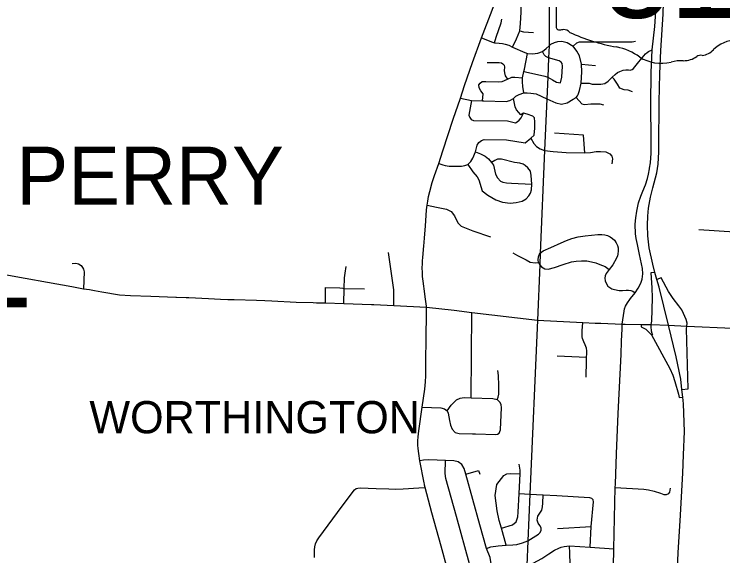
# Model space of a CAD drawing. Extents: x 1755200 to 1902939, y 644115 to 788070.
# Drawn here: x 1808355 to 1819343, y 757899 to 766300 of the extents above; entities that cross this region are included whole.
import ezdxf

# ---------------------------------------------------------------- set-up
doc = ezdxf.new("R2010")
doc.units = 0
for name, color, linetype in [('GM_X_City_Street', 7, 'Continuous'), ('GM_X_Corporation_Text', 7, 'Continuous'), ('GM_X_County_Road', 7, 'Continuous'), ('GM_X_Interchange_Ramps', 7, 'Continuous'), ('GM_X_State_Route', 7, 'Continuous'), ('GM_X_State_Shield', 7, 'Continuous'), ('GM_X_Township', 7, 'Continuous'), ('GM_X_Township_Text', 7, 'Continuous')]:
    doc.layers.add(name, color=color, linetype=linetype)

msp = doc.modelspace()

# ---------------------------------------------------------------- linework, layer by layer
at = {"layer": 'GM_X_City_Street'}
for points in [[(1818228, 764900), (1818228, 764902), (1818231, 765395), (1818249, 765747), (1818286, 766109), (1818306, 766340), (1818311, 766478), (1818310, 766621), (1818297, 766761), (1818273, 766958), (1818252, 767058), (1818227, 767144), (1818174, 767308), (1818073, 767603), (1818052, 767692), (1818038, 767786), (1818032, 767887), (1818045, 768024)], [(1816081, 765789), (1816144, 765918), (1816194, 766040), (1816208, 766154), (1816215, 766329), (1816223, 766542), (1816225, 766641), (1816241, 766690), (1816281, 766722), (1816331, 766734), (1816396, 766731), (1816445, 766743), (1816482, 766777), (1816498, 766825), (1816508, 767121), (1816509, 767181), (1816504, 767217), (1816486, 767247), (1816436, 767277), (1816423, 767280), (1816297, 767296)], [(1814711, 762759), (1814717, 762833), (1814731, 763011), (1814750, 763264), (1814758, 763337), (1814767, 763402), (1814781, 763474), (1814798, 763550), (1814837, 763687), (1814872, 763797), (1814940, 763985), (1814999, 764180), (1815164, 764673), (1815273, 764997), (1815338, 765195), (1815459, 765550), (1815603, 765933), (1815765, 766360), (1815831, 766555), (1815848, 766601), (1815849, 766605)], [(1815803, 765858), (1815827, 765945), (1815907, 766165), (1815916, 766223)], [(1816194, 766040), (1816250, 766024), (1816409, 766017)], [(1815603, 765933), (1815769, 765866), (1815803, 765858), (1815873, 765849), (1815927, 765846), (1815966, 765837), (1816024, 765820), (1816081, 765789), (1816274, 765705), (1816314, 765690), (1816392, 765685), (1816474, 765697), (1816548, 765720), (1816603, 765767), (1816649, 765810), (1816676, 765834), (1816731, 765863), (1816782, 765877), (1816848, 765880), (1816928, 765860), (1817023, 765802)], [(1817023, 765802), (1817078, 765856), (1817122, 765871), (1817301, 765869), (1817937, 765869), (1817986, 765882)], [(1816824, 765236), (1816846, 765322), (1816857, 765495), (1816851, 765534), (1816836, 765558), (1816803, 765577), (1816641, 765624), (1816598, 765642), (1816570, 765670), (1816548, 765720)], [(1817067, 765009), (1817087, 765035), (1817099, 765055), (1817121, 765115), (1817145, 765229), (1817157, 765406), (1817153, 765527), (1817118, 765652), (1817080, 765727), (1817023, 765802)], [(1817145, 765229), (1817268, 765229), (1817319, 765216), (1817384, 765212), (1817453, 765212), (1817515, 765226), (1817566, 765262), (1817628, 765321), (1817671, 765362), (1817711, 765394), (1817744, 765413), (1817797, 765430), (1817841, 765438), (1817878, 765435), (1817908, 765434), (1817936, 765440), (1817957, 765459), (1818040, 765559), (1818145, 765683), (1818169, 765706), (1818191, 765720), (1818249, 765747)], [(1816256, 765082), (1816243, 765180), (1816235, 765252), (1816237, 765313), (1816257, 765412), (1816265, 765445), (1816314, 765690)], [(1815690, 765550), (1815874, 765549), (1815909, 765544), (1815934, 765529), (1815951, 765507), (1815955, 765479), (1815950, 765429), (1815957, 765389), (1815970, 765346), (1816004, 765292)], [(1817153, 765527), (1817370, 765506)], [(1816257, 765412), (1816516, 765356), (1816583, 765338), (1816629, 765323), (1816704, 765284), (1816766, 765246), (1816824, 765236)], [(1815617, 764957), (1815627, 765063), (1815590, 765113), (1815563, 765157), (1815561, 765202), (1815579, 765232), (1815613, 765256), (1815667, 765254), (1815863, 765250), (1815923, 765256), (1816004, 765292), (1816071, 765321), (1816116, 765325), (1816237, 765313)], [(1817941, 765095), (1817874, 765122), (1817815, 765125), (1817748, 765155), (1817708, 765217), (1817656, 765294), (1817628, 765321)], [(1815637, 764957), (1815985, 764948), (1816039, 764961), (1816098, 764990), (1816131, 765026), (1816183, 765055), (1816256, 765082), (1816310, 765078), (1816366, 765077), (1816450, 765065), (1816614, 764988), (1816753, 764924), (1816841, 764905), (1816928, 764924), (1817022, 764982), (1817067, 765009)], [(1815273, 764997), (1815444, 764959), (1815617, 764957), (1815637, 764957)], [(1815444, 764959), (1815407, 764732), (1815420, 764699), (1815442, 764668), (1815479, 764652), (1816004, 764648), (1816127, 764616), (1816153, 764630), (1816183, 764654), (1816218, 764692), (1816250, 764765)], [(1816427, 764526), (1816430, 764629), (1816425, 764692), (1816395, 764717), (1816310, 764749), (1816250, 764765), (1816212, 764740), (1816178, 764774), (1816142, 764817), (1816123, 764865), (1816098, 764990)], [(1817067, 765009), (1817157, 764909), (1817197, 764898), (1817295, 764909), (1817438, 764907), (1817490, 764894)], [(1816365, 764376), (1816415, 764426), (1816425, 764481), (1816427, 764526)], [(1817201, 764149), (1817180, 764421), (1816732, 764452)], [(1815146, 763944), (1815293, 763943), (1815343, 763952), (1815388, 763970), (1815437, 764015), (1815467, 764065), (1815506, 764163), (1815536, 764266), (1815560, 764310), (1815599, 764341), (1815640, 764354), (1815990, 764349), (1816277, 764305), (1816365, 764376)], [(1816365, 764376), (1816411, 764292), (1816452, 764249), (1816510, 764214), (1816580, 764186), (1816713, 764170), (1816913, 764157), (1817201, 764149), (1817292, 764152), (1817377, 764171), (1817444, 764171), (1817527, 764164), (1817593, 764134), (1817621, 764099), (1817630, 764055), (1817623, 763977)], [(1815506, 764163), (1815585, 764134), (1815657, 764098), (1815710, 764054), (1815757, 763999), (1815787, 763957), (1815819, 763821), (1815851, 763763), (1815898, 763712), (1815934, 763694), (1815990, 763684), (1816066, 763677), (1816382, 763665)], [(1814940, 763985), (1815002, 763962), (1815037, 763953), (1815097, 763945), (1815146, 763944)], [(1815388, 763970), (1815468, 763853), (1815532, 763775), (1815560, 763733), (1815611, 763562), (1815699, 763491), (1815824, 763418), (1815924, 763383), (1816046, 763371), (1816140, 763378), (1816232, 763402), (1816295, 763437), (1816335, 763485), (1816359, 763525), (1816374, 763577), (1816382, 763665)], [(1816382, 763665), (1816373, 763797), (1816362, 763863), (1816318, 763916), (1816278, 763954), (1816246, 763976), (1816197, 763991), (1816115, 763997), (1815911, 764053), (1815849, 764051), (1815810, 764033), (1815757, 763999)], [(1817910, 761888), (1817983, 761980), (1818032, 762048), (1818070, 762128), (1818090, 762192), (1818096, 762230), (1818101, 762274), (1818099, 762353), (1818053, 762574), (1818019, 762730), (1817997, 762823), (1817990, 762893), (1817984, 763045), (1817993, 763140), (1818007, 763245), (1818035, 763373), (1818070, 763479), (1818102, 763557), (1818143, 763651), (1818174, 763749), (1818189, 763819), (1818206, 763900)], [(1814758, 763337), (1814905, 763309), (1815057, 763277), (1815131, 763238), (1815182, 763173), (1815232, 763065), (1815287, 763012), (1815362, 762980), (1815469, 762942), (1815738, 762845)], [(1816089, 762599), (1816158, 762557), (1816294, 762488), (1816357, 762456), (1816432, 762442), (1816483, 762448), (1816480, 762491), (1816486, 762538), (1816496, 762565), (1816512, 762594), (1816559, 762631), (1816677, 762683), (1816834, 762754), (1816919, 762792), (1817002, 762821), (1817102, 762846), (1817210, 762861), (1817308, 762874), (1817402, 762884), (1817465, 762884), (1817515, 762878), (1817557, 762867), (1817596, 762847), (1817633, 762822), (1817662, 762793), (1817687, 762753), (1817708, 762713), (1817718, 762676), (1817721, 762629), (1817717, 762580), (1817709, 762551), (1817696, 762518), (1817635, 762412), (1817579, 762342), (1817532, 762277), (1817518, 762242), (1817515, 762206), (1817520, 762162), (1817532, 762127), (1817561, 762083), (1817589, 762059), (1817620, 762042), (1817661, 762028), (1817735, 762015), (1817788, 762015), (1817843, 762021), (1817882, 762020), (1817918, 762014), (1817948, 762002), (1817983, 761980)], [(1818973, 762959), (1819523, 762926), (1819635, 762915), (1819636, 762915)], [(1814727, 761914), (1814720, 761962), (1814698, 762160), (1814688, 762231), (1814685, 762289), (1814683, 762370), (1814685, 762420), (1814688, 762472), (1814692, 762524), (1814707, 762705), (1814711, 762759)], [(1814241, 761983), (1814243, 762026), (1814158, 762604)], [(1809252, 762433), (1809254, 762434), (1809310, 762436), (1809350, 762427), (1809392, 762401), (1809416, 762373), (1809430, 762347), (1809441, 762303), (1809431, 762042)], [(1816483, 762448), (1816504, 762413), (1816532, 762382), (1816585, 762352), (1816634, 762345), (1816731, 762370), (1816867, 762419), (1816997, 762458), (1817070, 762469), (1817151, 762475), (1817232, 762472), (1817304, 762459), (1817372, 762442), (1817438, 762419), (1817516, 762384), (1817579, 762342)], [(1813487, 762281), (1813504, 762384)], [(1813465, 761813), (1813469, 762047), (1813476, 762213), (1813487, 762281)], [(1813184, 761821), (1813184, 762063), (1813406, 762053), (1813449, 762049)], [(1813449, 762049), (1813469, 762047), (1813787, 762039)], [(1814240, 761783), (1814240, 761799), (1814241, 761983)], [(1814749, 761757), (1814747, 761770), (1814727, 761914)], [(1815441, 760351), (1815449, 761673)], [(1817224, 760672), (1817231, 760921), (1817230, 760979), (1817232, 761032), (1817233, 761080), (1817228, 761122), (1817210, 761171), (1817187, 761220), (1817169, 761268), (1817163, 761296), (1817162, 761326), (1817164, 761386), (1817174, 761517)], [(1817677, 759012), (1817694, 759481), (1817719, 760106), (1817764, 761022), (1817774, 761230)], [(1814715, 759012), (1814711, 759030), (1814646, 759370), (1814629, 759488), (1814619, 759561), (1814615, 759615), (1814614, 759681), (1814619, 759744), (1814628, 759835), (1814683, 760204), (1814720, 760482), (1814733, 760595), (1814737, 760688), (1814740, 761006), (1814742, 761184)], [(1816775, 761001), (1817230, 760979)], [(1815842, 760323), (1815858, 760362), (1815868, 760404), (1815871, 760539), (1815863, 760696), (1815853, 760774)], [(1815069, 760147), (1815130, 760236), (1815213, 760318), (1815270, 760346), (1815333, 760354), (1815441, 760351)], [(1815441, 760351), (1815776, 760339), (1815842, 760323)], [(1815877, 759801), (1815898, 759852), (1815910, 760201), (1815905, 760242), (1815888, 760279), (1815842, 760323)], [(1814683, 760204), (1814972, 760193), (1815025, 760179), (1815069, 760147), (1815082, 760109), (1815105, 759998), (1815120, 759923), (1815144, 759861), (1815192, 759813), (1815257, 759795), (1815463, 759790), (1815508, 759789)], [(1815508, 759789), (1815822, 759781), (1815851, 759787), (1815877, 759801)], [(1815759, 757711), (1815737, 757872), (1815676, 758014), (1815573, 758379), (1815357, 759165), (1815330, 759254), (1815295, 759314), (1815239, 759356), (1815171, 759373), (1815044, 759376), (1814784, 759387), (1814704, 759380), (1814646, 759370)], [(1815261, 757284), (1815384, 757346), (1815455, 757403), (1815489, 757498), (1815475, 757603), (1815415, 757774), (1815211, 758507), (1815047, 759099), (1815036, 759178), (1815044, 759376)], [(1815910, 758327), (1816079, 758377), (1816139, 758428), (1816165, 758502), (1816169, 758576), (1816183, 758865), (1816198, 759169), (1816201, 759228), (1816187, 759321)], [(1815357, 759165), (1815556, 759220), (1815573, 759167)], [(1815981, 758062), (1815910, 758327), (1815876, 758445), (1815845, 758597), (1815812, 758836), (1815839, 759004), (1815949, 759145), (1815996, 759171), (1816052, 759176), (1816198, 759169)], [(1813009, 757871), (1813014, 757989), (1813016, 758039), (1813029, 758086), (1813048, 758130), (1813077, 758180), (1813370, 758572), (1813610, 758898), (1813633, 758922), (1813658, 758941), (1813685, 758950), (1813722, 758953), (1813969, 758944), (1814166, 758937), (1814266, 758935), (1814384, 758940), (1814627, 758951), (1814726, 758961)], [(1815609, 756712), (1815479, 756869), (1815394, 757030), (1815261, 757284), (1815145, 757498), (1815075, 757689), (1814974, 758051), (1814830, 758568), (1814726, 758961), (1814719, 758996), (1814715, 759012)], [(1817643, 757216), (1817642, 757462), (1817653, 758007), (1817675, 758956), (1817677, 759012)], [(1817675, 758956), (1818119, 758931), (1818188, 758922)], [(1818188, 758922), (1818191, 758922), (1818277, 758903), (1818377, 758872), (1818426, 758850), (1818468, 758849), (1818505, 758865), (1818523, 758887), (1818532, 758947)], [(1815676, 758014), (1815748, 758036), (1815858, 758055), (1815981, 758062), (1816088, 758068), (1816149, 758075), (1816236, 758098), (1816321, 758133), (1816483, 758236), (1816505, 758254), (1816527, 758290), (1816527, 758332), (1816505, 758368), (1816478, 758406), (1816464, 758451), (1816472, 758512), (1816506, 758562), (1816536, 758606), (1816547, 758658), (1816551, 758716), (1816557, 758843)], [(1816183, 758865), (1816352, 758855), (1816557, 758843), (1816767, 758832), (1817276, 758802), (1817305, 758793), (1817334, 758765)], [(1817285, 758031), (1817303, 758354), (1817339, 758737), (1817334, 758765)], [(1816781, 758323), (1817303, 758354)], [(1815475, 757603), (1815645, 757677), (1815759, 757711), (1815996, 757712), (1816074, 757711), (1816224, 757729), (1816304, 757749), (1816403, 757784), (1816537, 757856), (1816646, 757927), (1816732, 757986), (1816798, 758018), (1816835, 758031), (1816881, 758044), (1816965, 758053), (1817285, 758031), (1817653, 758007)], [(1817124, 757695), (1817034, 757700), (1816993, 757705), (1816977, 757728), (1816975, 757770), (1816968, 757942), (1816965, 758053)]]:
    msp.add_lwpolyline(points, dxfattribs=at)
at = {"layer": 'GM_X_County_Road'}
for points in [[(1818206, 763900), (1818208, 763910), (1818223, 763994), (1818232, 764143), (1818234, 764354), (1818228, 764900)], [(1817774, 761230), (1817783, 761421), (1817781, 761494), (1817811, 761694), (1817820, 761728), (1817835, 761769), (1817862, 761822), (1817900, 761875), (1817910, 761888)], [(1814742, 761184), (1814749, 761757)]]:
    msp.add_lwpolyline(points, dxfattribs=at)
at = {"layer": 'GM_X_Interchange_Ramps'}
for points in [[(1818290, 762294), (1818224, 762287), (1818244, 762055), (1818247, 761902), (1818237, 761538), (1818227, 761485)], [(1818782, 761462), (1818788, 761505), (1818775, 761562), (1818735, 761659), (1818705, 761715), (1818662, 761775), (1818575, 761888), (1818501, 761999), (1818389, 762210), (1818321, 762184)], [(1818078, 761489), (1818078, 761449), (1818149, 761412), (1818202, 761365), (1818232, 761334), (1818237, 761324), (1818522, 760803), (1818569, 760701), (1818598, 760605), (1818655, 760408), (1818666, 760354), (1818722, 760357)], [(1818227, 761485), (1818224, 761450), (1818224, 761449), (1818230, 761391), (1818242, 761351), (1818251, 761333), (1818237, 761324)], [(1818709, 760477), (1818806, 760487), (1818777, 761420), (1818782, 761462)]]:
    msp.add_lwpolyline(points, dxfattribs=at)
at = {"layer": 'GM_X_State_Route'}
for points in [[(1818416, 766299), (1818418, 766330), (1818437, 766799), (1818472, 767306), (1818499, 767607), (1818534, 767867)], [(1818498, 761474), (1818353, 762066), (1818321, 762184), (1818290, 762294), (1818255, 762424), (1818201, 762677), (1818178, 762864), (1818173, 763026), (1818179, 763167), (1818189, 763291), (1818223, 763462), (1818257, 763605), (1818317, 763840), (1818339, 763976), (1818348, 764167), (1818350, 764250), (1818358, 764940), (1818364, 765375), (1818383, 765736), (1818416, 766299)], [(1808137, 762275), (1808210, 762262), (1808525, 762203), (1808874, 762141), (1809249, 762074), (1809431, 762042), (1809525, 762027), (1809599, 762014)], [(1809599, 762014), (1809714, 761993), (1809986, 761945), (1810158, 761935), (1810473, 761924), (1810864, 761911)], [(1810864, 761911), (1810871, 761911), (1811023, 761905)], [(1811023, 761905), (1811065, 761903), (1811370, 761888), (1811553, 761881)], [(1811553, 761881), (1811667, 761877), (1811765, 761874)], [(1811765, 761874), (1812112, 761862), (1812242, 761857), (1812348, 761852)], [(1812348, 761852), (1812729, 761834), (1812989, 761827)], [(1812989, 761827), (1812993, 761827), (1813042, 761825)], [(1813042, 761825), (1813184, 761821), (1813465, 761813), (1813896, 761796)], [(1813896, 761796), (1813930, 761795), (1814240, 761783), (1814749, 761757), (1815175, 761710), (1815449, 761673), (1816467, 761552), (1817174, 761517), (1817361, 761509)], [(1817361, 761509), (1817450, 761506), (1817781, 761494), (1817830, 761494)], [(1817830, 761494), (1818078, 761489), (1818227, 761485), (1818498, 761474)], [(1818498, 761474), (1818782, 761462), (1819491, 761432)], [(1818709, 760477), (1818691, 760641), (1818617, 760984), (1818498, 761474)], [(1818734, 759463), (1818749, 759829), (1818733, 760256), (1818722, 760357), (1818709, 760477)], [(1818617, 757147), (1818652, 757950), (1818681, 758442), (1818723, 759181), (1818734, 759463)]]:
    msp.add_lwpolyline(points, dxfattribs=at)
at = {"layer": 'GM_X_State_Shield'}
msp.add_line((1816761, 768208), (1816761, 766094), dxfattribs=at)
for centre, major_axis, start_param, end_param in [((1816801, 766090), (40.7, 0), 3.00124, 4.508301), ((1816807, 766306), (310, 0), 4.665946, 4.897461), ((1816871, 765972), (112, 0), 0.519207, 1.627899), ((1818284, 767871), (2665, 0), 4.195997, 4.488961), ((1819597, 765501), (506, 0), 1.647645, 2.488434), ((1817489, 765145), (834, 0), 0.823519, 1.323587), ((1818957, 765890), (298, 0), 4.937069, 5.64225), ((1818391, 765962), (529, 0), 4.026481, 4.996735), ((1818736, 765804), (282, 0), 4.691044, 5.507374), ((1818991, 765599), (79.4, 0), 1.147584, 2.315152), ((1818697, 765231), (435, 0), 1.495662, 1.94098)]:
    msp.add_ellipse(centre, major_axis=major_axis, ratio=0.8, start_param=start_param, end_param=end_param, dxfattribs=at)
at = {"layer": 'GM_X_Township'}
msp.add_lwpolyline([(1816650, 766447), (1816649, 765810), (1816641, 765624), (1816629, 765323), (1816614, 764988), (1816580, 764186), (1816512, 762594), (1816504, 762413), (1816467, 761552), (1816352, 758855), (1816321, 758133), (1816304, 757749)], dxfattribs=at)

# ---------------------------------------------------------------- texts
at = {"layer": 'GM_X_Corporation_Text'}
msp.add_text('WORTHINGTON', height=500, rotation=0, dxfattribs=at).set_placement((1809521, 759799))
at = {"layer": 'GM_X_State_Shield'}
for s, p in [('315', (1817490, 766243)), ('161', (1805534, 761751))]:
    msp.add_text(s, height=1392.2, dxfattribs=at).set_placement(p)
at = {"layer": 'GM_X_Township_Text'}
msp.add_text('PERRY', height=900, rotation=0, dxfattribs=at).set_placement((1808390, 763345))

doc.saveas('drawing.dxf')
